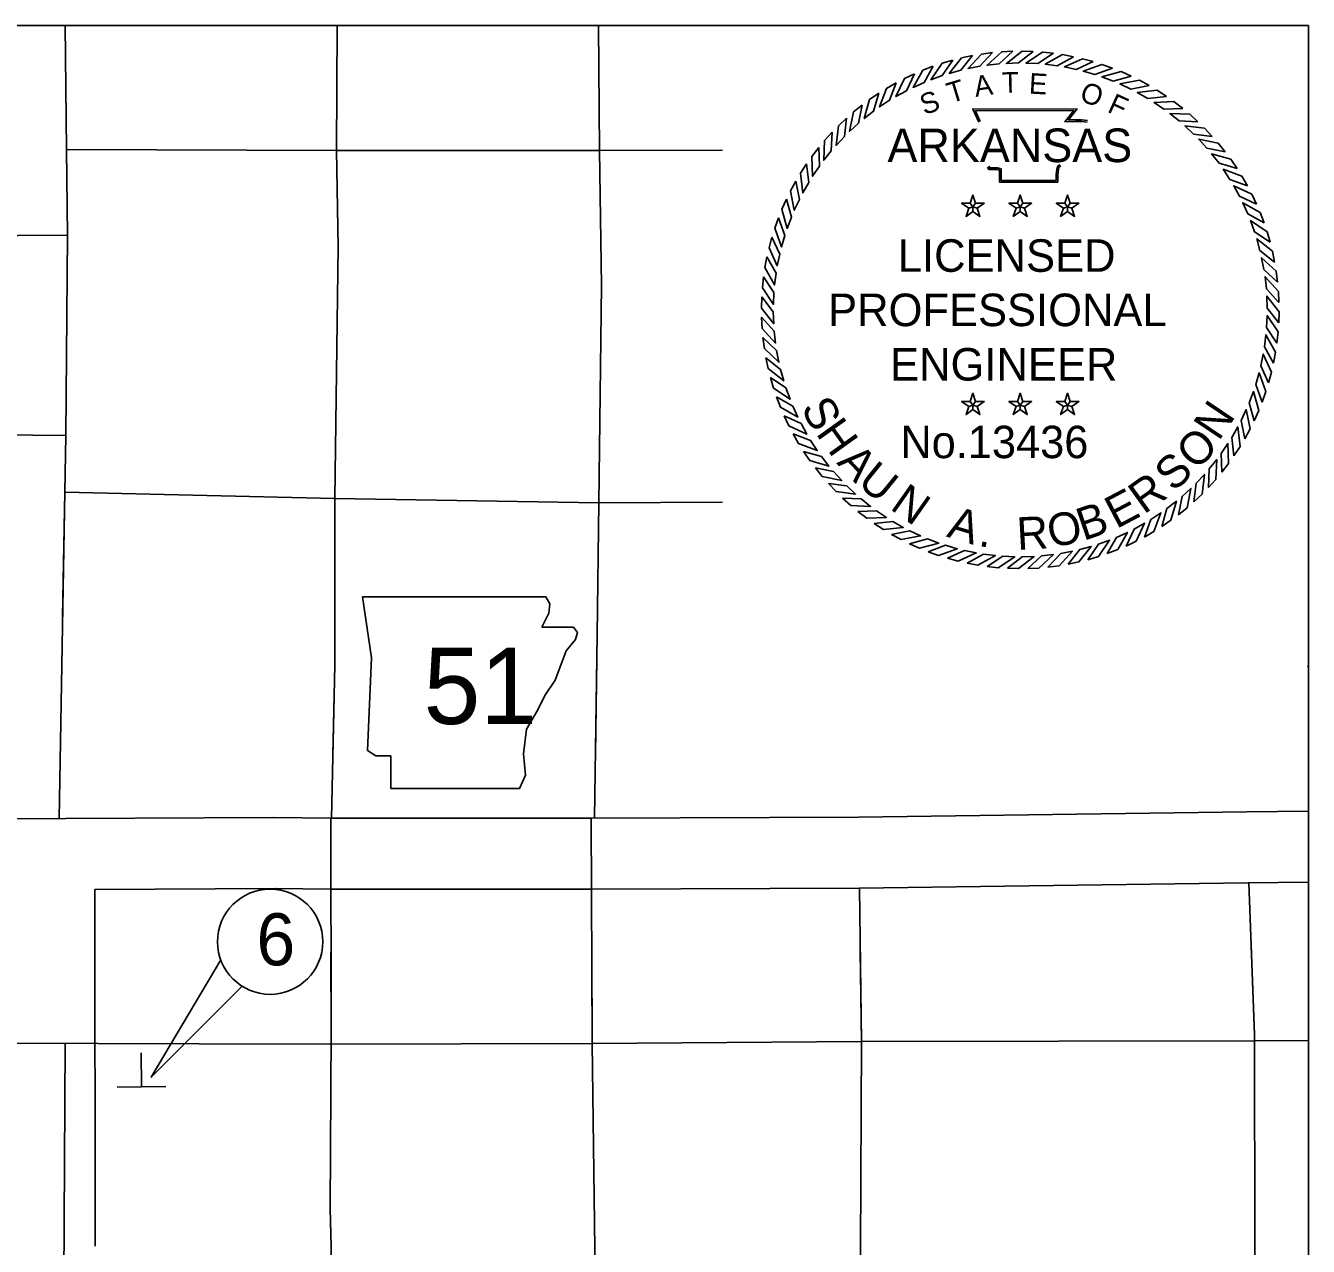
# Model space of a CAD drawing. Extents: x 988392 to 996681, y 1838707 to 1844440.
# Drawn here: x 993499 to 995125, y 1842892 to 1844440 of the extents above; entities that cross this region are included whole.
import ezdxf

# ---------------------------------------------------------------- set-up
doc = ezdxf.new("R2010")
doc.units = 0
for name, color, linetype in [('G-ANNO-SYMB', 7, 'Continuous'), ('G-Border-Sheet', 7, 'Continuous'), ('Level 21', 7, 'Continuous'), ('Level 3', 7, 'Continuous'), ('Level 33', 7, 'Continuous'), ('Level 8', 7, 'Continuous'), ('R_Draft', 7, 'Continuous')]:
    doc.layers.add(name, color=color, linetype=linetype)

msp = doc.modelspace()

# ---------------------------------------------------------------- linework, layer by layer
at = {"layer": 'G-ANNO-SYMB'}
for points in [[(994699, 1844401.6), (994685.2, 1844398.7), (994669.6, 1844379), (994684.3, 1844383)], [(994724.5, 1844405.3), (994710.5, 1844403.5), (994693.4, 1844385.1), (994708.4, 1844388)], [(994750.2, 1844407.1), (994736.1, 1844406.4), (994717.6, 1844389.4), (994732.7, 1844391)], [(994776, 1844406.8), (994761.9, 1844407.2), (994742.1, 1844391.7), (994757.3, 1844392.2)], [(994801.7, 1844404.5), (994787.6, 1844406), (994766.7, 1844392.1), (994781.9, 1844391.4)], [(994827.1, 1844400.2), (994813.2, 1844402.8), (994791.2, 1844390.6), (994806.3, 1844388.7)], [(994649.3, 1844388.1), (994636.1, 1844383.1), (994623.8, 1844361.2), (994637.7, 1844367.5)], [(994673.9, 1844395.8), (994660.4, 1844391.8), (994646.3, 1844371), (994660.7, 1844376.2)], [(994852, 1844393.9), (994838.4, 1844397.6), (994815.5, 1844387.2), (994830.5, 1844384.1)], [(994876.5, 1844385.7), (994863.2, 1844390.4), (994839.5, 1844381.8), (994854.2, 1844377.6)], [(994602.3, 1844367.1), (994590.1, 1844360), (994581.3, 1844336.5), (994594, 1844344.9)], [(994625.4, 1844378.5), (994612.7, 1844372.5), (994602, 1844349.7), (994615.4, 1844357)], [(994900.2, 1844375.6), (994887.3, 1844381.3), (994863, 1844374.6), (994877.3, 1844369.2)], [(994923, 1844363.6), (994910.6, 1844370.4), (994885.9, 1844365.6), (994899.7, 1844359.1)], [(994580.2, 1844353.8), (994568.6, 1844345.9), (994561.7, 1844321.7), (994573.7, 1844331)], [(994944.8, 1844349.9), (994933, 1844357.7), (994908, 1844354.8), (994921.2, 1844347.3)], [(994559.2, 1844338.9), (994548.2, 1844330.1), (994543.2, 1844305.4), (994554.5, 1844315.7)], [(994965.5, 1844334.6), (994954.3, 1844343.2), (994929.2, 1844342.3), (994941.8, 1844333.7)], [(994539.5, 1844322.4), (994529.2, 1844312.7), (994526.1, 1844287.7), (994536.6, 1844298.9)], [(994984.9, 1844317.6), (994974.4, 1844327.1), (994949.3, 1844328.2), (994961.2, 1844318.7)], [(994521, 1844304.4), (994511.6, 1844293.9), (994510.5, 1844268.8), (994520, 1844280.7)], [(995002.9, 1844299.2), (994993.2, 1844309.5), (994968.3, 1844312.5), (994979.4, 1844302.1)], [(995019.4, 1844279.5), (995010.6, 1844290.4), (994985.9, 1844295.5), (994996.2, 1844284.2)], [(994504.1, 1844285), (994495.5, 1844273.8), (994496.4, 1844248.6), (994504.9, 1844261.3)], [(995034.4, 1844258.4), (995026.4, 1844270.1), (995002.2, 1844277), (995011.6, 1844265)], [(994488.7, 1844264.3), (994481, 1844252.5), (994483.9, 1844227.5), (994491.4, 1844240.7)], [(995047.6, 1844236.3), (995040.6, 1844248.6), (995017, 1844257.4), (995025.4, 1844244.6)], [(994475, 1844242.5), (994468.3, 1844230.1), (994473.1, 1844205.4), (994479.6, 1844219.2)], [(994699.6, 1844209.7), (994703, 1844214.4), (994699.6, 1844224.7), (994696.2, 1844214.4)], [(994759.6, 1844209.7), (994763, 1844214.4), (994759.6, 1844224.7), (994756.2, 1844214.4)], [(994819.6, 1844209.7), (994823, 1844214.4), (994819.6, 1844224.7), (994816.2, 1844214.4)], [(995059, 1844213.3), (995053, 1844226), (995030.2, 1844236.6), (995037.6, 1844223.3)], [(994463.1, 1844219.6), (994457.3, 1844206.7), (994464.1, 1844182.5), (994469.4, 1844196.8)], [(994699.6, 1844209.7), (994696.2, 1844214.4), (994685.3, 1844214.4), (994694.2, 1844208)], [(994699.6, 1844209.7), (994694.2, 1844208), (994690.8, 1844197.6), (994699.6, 1844204)], [(994699.6, 1844209.7), (994705.1, 1844208), (994713.9, 1844214.4), (994703, 1844214.4)], [(994699.6, 1844209.7), (994699.6, 1844204), (994708.4, 1844197.6), (994705.1, 1844208)], [(994759.6, 1844209.7), (994756.2, 1844214.4), (994745.3, 1844214.4), (994754.2, 1844208)], [(994759.6, 1844209.7), (994754.2, 1844208), (994750.8, 1844197.6), (994759.6, 1844204)], [(994759.6, 1844209.7), (994765.1, 1844208), (994773.9, 1844214.4), (994763, 1844214.4)], [(994759.6, 1844209.7), (994759.6, 1844204), (994768.4, 1844197.6), (994765.1, 1844208)], [(994819.6, 1844209.7), (994816.2, 1844214.4), (994805.3, 1844214.4), (994814.2, 1844208)], [(994819.6, 1844209.7), (994814.2, 1844208), (994810.8, 1844197.6), (994819.6, 1844204)], [(994819.6, 1844209.7), (994825.1, 1844208), (994833.9, 1844214.4), (994823, 1844214.4)], [(994819.6, 1844209.7), (994819.6, 1844204), (994828.4, 1844197.6), (994825.1, 1844208)], [(995068.6, 1844189.4), (995063.6, 1844202.5), (995041.7, 1844214.9), (995048, 1844201)], [(994453, 1844195.9), (994448.3, 1844182.6), (994456.9, 1844159), (994461.1, 1844173.6)], [(995076.3, 1844164.8), (995072.4, 1844178.3), (995051.5, 1844192.4), (995056.7, 1844178)], [(994444.8, 1844171.5), (994441.1, 1844157.9), (994451.5, 1844135), (994454.6, 1844149.9)], [(995082.1, 1844139.6), (995079.2, 1844153.5), (995059.5, 1844169.1), (995063.5, 1844154.4)], [(994438.5, 1844146.5), (994435.9, 1844132.7), (994448.1, 1844110.7), (994450, 1844125.8)], [(995085.9, 1844114.2), (995084, 1844128.2), (995065.6, 1844145.3), (995068.5, 1844130.3)], [(994434.2, 1844121.1), (994432.7, 1844107.1), (994446.6, 1844086.1), (994447.3, 1844101.3)], [(995087.6, 1844088.5), (995086.9, 1844102.5), (995069.9, 1844121.1), (995071.6, 1844105.9)], [(994431.9, 1844095.5), (994431.5, 1844081.4), (994447, 1844061.5), (994446.5, 1844076.8)], [(995087.3, 1844062.7), (995087.7, 1844076.8), (995072.2, 1844096.6), (995072.7, 1844081.4)], [(994431.6, 1844069.7), (994432.3, 1844055.6), (994449.3, 1844037.1), (994447.6, 1844052.2)], [(995085, 1844037), (995086.5, 1844051.1), (995072.7, 1844072), (995071.9, 1844056.8)], [(994433.4, 1844044), (994435.2, 1844030), (994453.6, 1844012.8), (994450.7, 1844027.8)], [(995080.7, 1844011.6), (995083.3, 1844025.5), (995071.1, 1844047.5), (995069.2, 1844032.4)], [(994437.1, 1844018.5), (994440, 1844004.7), (994459.7, 1843989), (994455.7, 1844003.7)], [(995074.4, 1843986.6), (995078.1, 1844000.3), (995067.7, 1844023.1), (995064.6, 1844008.2)], [(994442.9, 1843993.4), (994446.8, 1843979.9), (994467.7, 1843965.8), (994462.5, 1843980.1)], [(995066.2, 1843962.2), (995071, 1843975.5), (995062.4, 1843999.1), (995058.1, 1843984.5)], [(994450.6, 1843968.8), (994455.6, 1843955.6), (994477.5, 1843943.2), (994471.2, 1843957.1)], [(994699.6, 1843958.5), (994696.2, 1843963.1), (994685.3, 1843963.1), (994694.2, 1843956.7)], [(994699.6, 1843958.5), (994703, 1843963.1), (994699.6, 1843973.5), (994696.2, 1843963.1)], [(994699.6, 1843958.5), (994705.1, 1843956.7), (994713.9, 1843963.1), (994703, 1843963.1)], [(994759.6, 1843958.5), (994756.2, 1843963.1), (994745.3, 1843963.1), (994754.2, 1843956.7)], [(994759.6, 1843958.5), (994763, 1843963.1), (994759.6, 1843973.5), (994756.2, 1843963.1)], [(994759.6, 1843958.5), (994765.1, 1843956.7), (994773.9, 1843963.1), (994763, 1843963.1)], [(994819.6, 1843958.5), (994816.2, 1843963.1), (994805.3, 1843963.1), (994814.2, 1843956.7)], [(994819.6, 1843958.5), (994823, 1843963.1), (994819.6, 1843973.5), (994816.2, 1843963.1)], [(994819.6, 1843958.5), (994825.1, 1843956.7), (994833.9, 1843963.1), (994823, 1843963.1)], [(995056.1, 1843938.5), (995061.9, 1843951.4), (995055.2, 1843975.6), (995049.8, 1843961.4)], [(994460.2, 1843944.9), (994466.2, 1843932.1), (994489, 1843921.5), (994481.7, 1843934.9)], [(994699.6, 1843958.5), (994694.2, 1843956.7), (994690.8, 1843946.4), (994699.6, 1843952.8)], [(994699.6, 1843958.5), (994699.6, 1843952.8), (994708.4, 1843946.4), (994705.1, 1843956.7)], [(994759.6, 1843958.5), (994754.2, 1843956.7), (994750.8, 1843946.4), (994759.6, 1843952.8)], [(994759.6, 1843958.5), (994759.6, 1843952.8), (994768.4, 1843946.4), (994765.1, 1843956.7)], [(994819.6, 1843958.5), (994814.2, 1843956.7), (994810.8, 1843946.4), (994819.6, 1843952.8)], [(994819.6, 1843958.5), (994819.6, 1843952.8), (994828.4, 1843946.4), (994825.1, 1843956.7)], [(995044.2, 1843915.7), (995050.9, 1843928.1), (995046.1, 1843952.8), (995039.6, 1843939)], [(995030.5, 1843893.9), (995038.2, 1843905.7), (995035.3, 1843930.7), (995027.8, 1843917.4)], [(994471.6, 1843921.8), (994478.6, 1843909.6), (994502.2, 1843900.8), (994493.8, 1843913.5)], [(994484.8, 1843899.7), (994492.8, 1843888.1), (994517, 1843881.1), (994507.6, 1843893.2)], [(995015.1, 1843873.2), (995023.7, 1843884.4), (995022.8, 1843909.5), (995014.3, 1843896.9)], [(994998.2, 1843853.8), (995007.6, 1843864.2), (995008.7, 1843889.4), (994999.2, 1843877.5)], [(994499.8, 1843878.7), (994508.6, 1843867.7), (994533.3, 1843862.7), (994523, 1843874)], [(994979.8, 1843835.8), (994990, 1843845.4), (994993.1, 1843870.4), (994982.6, 1843859.3)], [(994516.3, 1843858.9), (994526, 1843848.7), (994550.9, 1843845.6), (994539.8, 1843856)], [(994960, 1843819.2), (994971, 1843828.1), (994976, 1843852.7), (994964.7, 1843842.5)], [(994534.3, 1843840.5), (994544.8, 1843831.1), (994569.9, 1843830), (994558, 1843839.5)], [(994939, 1843804.3), (994950.6, 1843812.3), (994957.6, 1843836.5), (994945.5, 1843827.1)], [(994553.7, 1843823.6), (994564.9, 1843815), (994590, 1843815.8), (994577.4, 1843824.4)], [(994916.9, 1843791.1), (994929.1, 1843798.1), (994937.9, 1843821.7), (994925.2, 1843813.3)], [(994574.4, 1843808.2), (994586.2, 1843800.5), (994611.2, 1843803.3), (994598, 1843810.9)], [(994596.2, 1843794.5), (994608.6, 1843787.8), (994633.3, 1843792.6), (994619.5, 1843799)], [(994893.8, 1843779.6), (994906.5, 1843785.7), (994917.2, 1843808.5), (994903.8, 1843801.1)], [(994619.1, 1843782.6), (994631.9, 1843776.8), (994656.2, 1843783.5), (994641.9, 1843788.9)], [(994845.3, 1843762.3), (994858.8, 1843766.3), (994872.9, 1843787.2), (994858.6, 1843782)], [(994869.9, 1843770), (994883.1, 1843775.1), (994895.4, 1843797), (994881.6, 1843790.7)], [(994642.8, 1843772.5), (994656, 1843767.7), (994679.7, 1843776.3), (994665, 1843780.6)], [(994667.2, 1843764.2), (994680.8, 1843760.6), (994703.7, 1843771), (994688.7, 1843774.1)], [(994692.2, 1843758), (994706, 1843755.4), (994728, 1843767.5), (994712.9, 1843769.5)], [(994717.6, 1843753.7), (994731.6, 1843752.1), (994752.6, 1843766), (994737.3, 1843766.7)], [(994743.2, 1843751.4), (994757.3, 1843751), (994777.1, 1843766.4), (994761.9, 1843766)], [(994769, 1843751.1), (994783.1, 1843751.8), (994801.6, 1843768.8), (994786.5, 1843767.1)], [(994794.7, 1843752.8), (994808.7, 1843754.6), (994825.8, 1843773), (994810.9, 1843770.2)], [(994820.2, 1843756.6), (994834, 1843759.5), (994849.6, 1843779.2), (994834.9, 1843775.1)]]:
    msp.add_lwpolyline(points, close=True, dxfattribs=at)
for points in [[(994707, 1844317.2), (994699.4, 1844333.8), (994831.7, 1844333.9), (994820.7, 1844320), (994829.7, 1844320.1), (994837.2, 1844320.2), (994844.7, 1844319.4)], [(994708.9, 1844318.1), (994702.7, 1844331.7), (994827.4, 1844331.8), (994816.3, 1844317.8), (994829.7, 1844318), (994837.1, 1844318.1), (994844.5, 1844317.3)], [(994810.9, 1844261.8), (994808.6, 1844259.9), (994807.9, 1844257.2), (994807.1, 1844250.3), (994807.1, 1844241.2), (994733.2, 1844241.2), (994733.2, 1844253.5), (994733.2, 1844256.3), (994730.2, 1844257.2), (994719.7, 1844257.2), (994717.9, 1844260)], [(994809.6, 1844263.4), (994806.8, 1844261.1), (994805.8, 1844257.6), (994805, 1844250.4), (994805, 1844243.3), (994735.3, 1844243.3), (994735.3, 1844253.5), (994735.3, 1844257.8), (994730.6, 1844259.3), (994720.9, 1844259.3), (994719.6, 1844261.2)]]:
    msp.add_lwpolyline(points, dxfattribs=at)
at = {"layer": 'G-Border-Sheet'}
msp.add_lwpolyline([(995124.8, 1844439.6), (989844.9, 1844439.6), (989844.9, 1838706.8), (995124.8, 1838706.8)], close=True, dxfattribs=at)
at = {"layer": 'Level 21'}
for p, q in [((993925.6, 1843715.3), (993937.3, 1843637.8)), ((994163.4, 1843706.3), (994158.1, 1843715.2)), ((994162.1, 1843694.6), (994163.4, 1843706.3)), ((994153.1, 1843676.6), (994162.1, 1843694.6)), ((994193.1, 1843676.6), (994153.1, 1843676.6)), ((994198.3, 1843670.1), (994193.1, 1843676.6)), ((994195.7, 1843661), (994198.3, 1843670.1)), ((994184.1, 1843646.8), (994195.7, 1843661)), ((993937.3, 1843637.8), (993932.1, 1843520.2)), ((994177.6, 1843630), (994184.1, 1843646.8)), ((994169.9, 1843609.4), (994177.6, 1843630)), ((994157, 1843590), (994169.9, 1843609.4)), ((994147.9, 1843571.9), (994157, 1843590)), ((994133.7, 1843547.3), (994147.9, 1843571.9)), ((994129.8, 1843516.3), (994133.7, 1843547.3)), ((993932.1, 1843520.2), (993942.4, 1843513.7)), ((993942.4, 1843513.7), (993961.8, 1843513.7)), ((993961.8, 1843513.7), (993961.8, 1843472.4)), ((994132.4, 1843489.2), (994129.8, 1843516.3)), ((994124.6, 1843472.4), (994132.4, 1843489.2)), ((993961.8, 1843472.4), (994124.6, 1843472.4))]:
    msp.add_line(p, q, dxfattribs=at)
msp.add_lwpolyline([(993925.6, 1843715.3), (994158.1, 1843715.2)], dxfattribs=at)
at = {"layer": 'Level 3'}
for p, q in [((993645.5, 1843094.9), (993645, 1843137.2)), ((993676.3, 1843094.4), (993614.5, 1843093.6))]:
    msp.add_line(p, q, dxfattribs=at)
at = {"layer": 'Level 33'}
msp.add_line((991873.8, 1843153.5), (993718.5, 1843148.4), dxfattribs=at)
for points in [[(993548.8, 1844439.6), (993550.3, 1844282.5)], [(993548.8, 1844439.6), (993550.3, 1844282.5)], [(993893.6, 1844439.6), (993892.8, 1844281.3)], [(993893.6, 1844439.6), (993892.8, 1844281.3)], [(994225.1, 1844439.6), (994226.2, 1844281.3)], [(994225.1, 1844439.6), (994226.2, 1844281.3)], [(993550.3, 1844282.5), (993551.7, 1844173.8), (993549.4, 1843920), (993548.3, 1843848), (993541.1, 1843434.3)], [(993550.3, 1844282.5), (993551.7, 1844173.8), (993549.4, 1843920), (993548.3, 1843848), (993545.5, 1843690.4)], [(993550.3, 1844282.5), (993892.8, 1844281.3), (994226.2, 1844281.3), (994382.3, 1844281.5)], [(993550.3, 1844282.5), (993892.8, 1844281.3), (994226.2, 1844281.3), (994382.3, 1844281.5)], [(993892.8, 1844281.3), (993895, 1844159.1), (993890.5, 1843840.1), (993890.5, 1843628.5), (993886.4, 1843434.5)], [(993892.8, 1844281.3), (993895, 1844159.1), (993890.5, 1843840.1), (993890.5, 1843628.5), (993888.1, 1843514.5)], [(994226.2, 1844281.3), (994228.9, 1844110.2), (994225.5, 1843834.6)], [(994226.2, 1844281.3), (994228.9, 1844110.2), (994225.5, 1843834.6)], [(993551.7, 1844173.8), (993173, 1844171.5), (992935.9, 1844172.6), (992695.2, 1844173.8), (992501.3, 1844174.6)], [(993551.7, 1844173.8), (993173, 1844171.5), (992935.9, 1844172.6), (992695.2, 1844173.8), (992581.3, 1844174.3)], [(992501.3, 1843924.1), (992691.8, 1843926), (992931.4, 1843922.6), (993171, 1843923.8), (993549.4, 1843920)], [(992581.3, 1843924.9), (992691.8, 1843926), (992931.4, 1843922.6), (993171, 1843923.8), (993549.4, 1843920)], [(993548.3, 1843848), (993890.5, 1843840.1), (994225.5, 1843834.6), (994382.3, 1843835.4)], [(993548.3, 1843848), (993890.5, 1843840.1), (994225.5, 1843834.6), (994382.3, 1843835.4)], [(994225.5, 1843834.6), (994223.2, 1843667.2), (994219.7, 1843434.6)], [(994225.5, 1843834.6), (994223.2, 1843667.2), (994220.9, 1843514.7)], [(995124.8, 1843625.4), (995124.1, 1843628.3)], [(993885.4, 1843434.5), (993885.9, 1843164.2), (993884.8, 1842939.4), (993885.9, 1842891.3), (993883.7, 1842628.9), (993880.3, 1842369.2), (993878, 1842103.4), (993878, 1841871.4), (993878, 1841621.4), (993878, 1841384.9), (993879.2, 1841271.4), (993872.4, 1841170.7), (993866.7, 1841142.4), (993857.7, 1841116.4), (993823.8, 1841061), (993769.5, 1840997.6), (993713, 1840933.1), (993663.9, 1840879.5)], [(994217, 1843148.7), (994215.7, 1843434.7)], [(994558.4, 1843151.3), (994555.7, 1843345.9)], [(995056.7, 1843160.1), (995049.3, 1843352.8)], [(993885.7, 1843264.5), (993885.9, 1843164.2), (993884.8, 1842939.4), (993885.9, 1842891.3), (993883.7, 1842628.9), (993880.3, 1842369.2), (993878, 1842103.4), (993878, 1841871.4), (993878, 1841621.4), (993878, 1841384.9), (993879.2, 1841271.4), (993872.4, 1841170.7), (993866.7, 1841142.4), (993857.7, 1841116.4), (993823.8, 1841061), (993769.5, 1840997.6), (993713, 1840933.1), (993663.9, 1840879.5)], [(994217, 1843148.7), (994216.5, 1843264.7)], [(994558.4, 1843151.3), (994556.8, 1843265.9)], [(995056.7, 1843160.1), (995052.4, 1843272.8)], [(993718.5, 1843148.4), (993884, 1843147.9), (994217, 1843148.7), (994558.4, 1843151.3), (995056.8, 1843152.4), (995124.8, 1843152.6)], [(993718.5, 1843148.4), (993884, 1843147.9), (994217, 1843148.7), (994558.4, 1843151.3), (995056.8, 1843152.4), (995124.8, 1843152.6)], [(994217, 1843148.7), (994220.4, 1842888.5), (994220.4, 1842624.5)], [(994217, 1843148.7), (994220.4, 1842888.5), (994220.4, 1842624.5)], [(994559.2, 1842106.7), (994561.6, 1842366), (994558.2, 1842622.8), (994557, 1842889.1), (994558.4, 1843151.3)], [(994559.2, 1842106.7), (994561.6, 1842366), (994558.2, 1842622.8), (994557, 1842889.1), (994558.4, 1843151.3)], [(994559.2, 1842106.7), (994742.7, 1842103.5), (994845.6, 1842106.9), (994902.1, 1842109.2), (994958.6, 1842129.5), (995016.3, 1842180.4), (995044.5, 1842256.3), (995054.7, 1842334.3), (995054.7, 1842363.8), (995058.1, 1842565.2), (995058.1, 1842622.2), (995056.9, 1842890.4), (995056.7, 1843160.1)], [(994559.2, 1842106.7), (994742.7, 1842103.5), (994845.6, 1842106.9), (994902.1, 1842109.2), (994958.6, 1842129.5), (995016.3, 1842180.4), (995044.5, 1842256.3), (995054.7, 1842334.3), (995054.7, 1842363.8), (995058.1, 1842565.2), (995058.1, 1842622.2), (995056.9, 1842890.4), (995056.7, 1843160.1)]]:
    msp.add_lwpolyline(points, dxfattribs=at)
at = {"layer": 'Level 8'}
msp.add_lwpolyline([(993746.1, 1843254.8), (993657.8, 1843106), (993773.3, 1843221.4)], dxfattribs=at)
msp.add_circle((993808.6, 1843277.9), 66.7, dxfattribs=at)
at = {"layer": 'R_Draft'}
for p, q in [((993812.5, 1843435.5), (993418.4, 1843433.5)), ((993586.5, 1843344.3), (993815.4, 1843345.5)), ((993586.6, 1842891.7), (993586.5, 1843344.3)), ((992230.7, 1843152.5), (993548.8, 1843148.9))]:
    msp.add_line(p, q, dxfattribs=at)
for points in [[(993812.8, 1843435.5), (993885.8, 1843434.5), (994215.8, 1843434.7), (994554.7, 1843435.9), (995047, 1843442.8), (995124.8, 1843443.4)], [(995124.8, 1843353.4), (995048, 1843352.8), (994555.5, 1843345.9), (994216, 1843344.7), (993885.2, 1843344.5), (993815, 1843345.5)], [(993548.8, 1843148.9), (993536, 1840894.4), (993531.9, 1840739.2)]]:
    msp.add_lwpolyline(points, dxfattribs=at)

# ---------------------------------------------------------------- texts
at = {"layer": 'G-ANNO-SYMB'}
for s, height, rotation, p in [('T', 26.1, 16.9015, (994671.3, 1844340.8)), ('A', 26.1, 8.6788, (994703, 1844349.1)), ('T', 26.1, 1.4789, (994736.7, 1844354.3)), ('E', 26.1, 356.672, (994770.1, 1844353.5)), ('O', 26.1, 341.2218, (994833.5, 1844344.5)), ('S', 26.1, 19.7726, (994638.1, 1844325.9)), ('F', 26.1, 335.3628, (994868.7, 1844330.8)), ('ARKANSAS', 42.61, 360, (994591.2, 1844266.5)), ('LICENSED', 41.25, 360, (994604.4, 1844127.4)), ('PROFESSIONAL', 41.25, 360, (994516, 1844058.5)), ('ENGINEER', 41.25, 360, (994594.6, 1843989.5)), ('S', 41.3, 298.1636, (994480.9, 1843954.8)), ('N', 41.3, 56.1007, (995011.2, 1843911.7)), ('H', 41.3, 305.619, (994499.7, 1843922.5)), ('No.13436', 41.09, 360, (994607.6, 1843891.1)), ('O', 41.3, 44.7757, (994982.5, 1843874.5)), ('A', 41.3, 313.4472, (994525.9, 1843884.8)), ('S', 41.3, 43.4878, (994954.2, 1843847.2)), ('U', 41.3, 320.9026, (994551.6, 1843857.9)), ('R', 41.3, 35.6597, (994916.3, 1843819.1)), ('N', 41.3, 324.9326, (994593.1, 1843827.2)), ('E', 41.3, 27.8315, (994881.4, 1843800.9)), ('B', 41.3, 18.885, (994839.7, 1843786)), ('A', 41.3, 343.0991, (994665.1, 1843791.8)), ('R', 41.3, 3.2287, (994756.2, 1843774.6)), ('O', 41.3, 11.4296, (994798.4, 1843777.2)), ('.', 41.3, 351.3, (994705.6, 1843779.8))]:
    msp.add_text(s, height=height, rotation=rotation, dxfattribs=at).set_placement(p)
at = {"layer": 'Level 21'}
msp.add_text('51', height=96.8, dxfattribs=at).set_placement((994003.1, 1843554))
at = {"layer": 'Level 8'}
msp.add_text('6', height=66, dxfattribs=at).set_placement((993791.3, 1843248))

doc.saveas('drawing.dxf')
